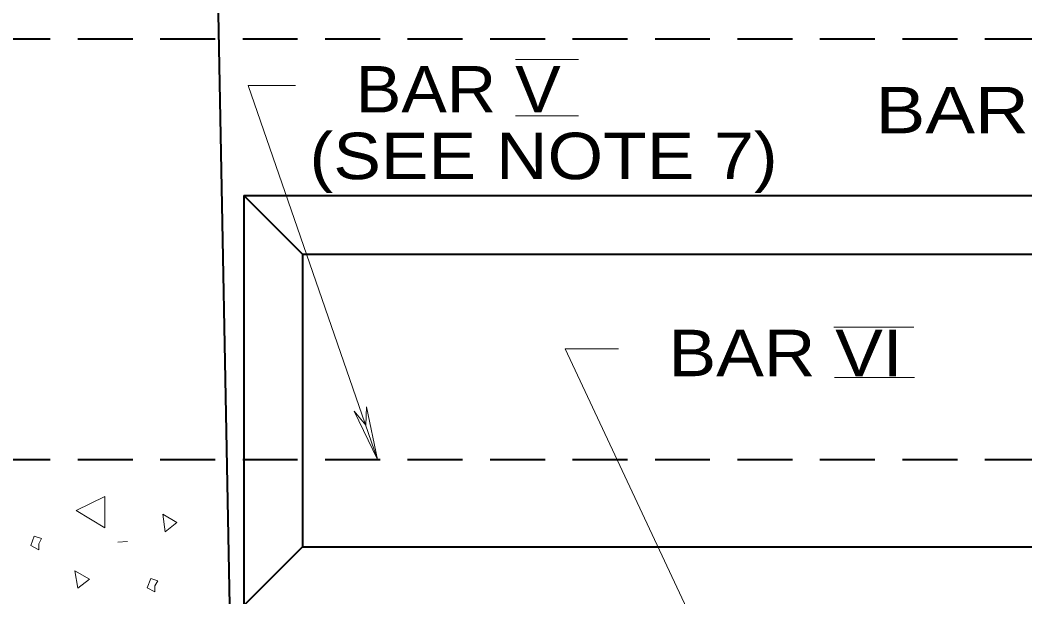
# Model space of a CAD drawing. Extents: x 312583 to 312854, y 144419 to 144597.
# Drawn here: x 312643.91 to 312660.36, y 144455.06 to 144464.5 of the extents above; entities that cross this region are included whole.
import ezdxf

# ---------------------------------------------------------------- set-up
doc = ezdxf.new("R2010")
doc.units = 0
doc.header["$LTSCALE"] = 0.3
doc.linetypes.add('MEDIUM_DASHED', pattern=[4.5, 3, -1.5])
doc.layers.add('1', color=7, linetype='Continuous', lineweight=25)
doc.layers.add('2', color=7, linetype='Continuous', lineweight=13)

msp = doc.modelspace()

# ---------------------------------------------------------------- linework, layer by layer
at = {"layer": '1', "lineweight": 40}
for p, q in [((312646.6198, 144493.0154), (312647.3405, 144454.9198)), ((312647.5781, 144461.6281), (312662.9115, 144461.6281)), ((312647.5781, 144461.6281), (312647.5781, 144454.9198)), ((312648.5365, 144460.6698), (312647.5781, 144461.6281)), ((312648.5365, 144460.6698), (312661.9531, 144460.6698)), ((312648.5365, 144460.6698), (312648.5365, 144455.8781)), ((312648.5365, 144455.8781), (312647.5781, 144454.9198)), ((312648.5365, 144455.8781), (312661.9531, 144455.8781))]:
    msp.add_line(p, q, dxfattribs=at)
at = {"layer": '1', "linetype": 'MEDIUM_DASHED', "lineweight": 40}
for p, q in [((312643.5071, 144464.1888), (312667.7031, 144464.1888)), ((312643.5071, 144457.3118), (312667.7031, 144457.3118))]:
    msp.add_line(p, q, dxfattribs=at)
at = {"layer": '1', "lineweight": 13}
msp.add_line((312645.5158, 144455.9548), (312645.6691, 144455.9701), dxfattribs=at)
for points in [[(312645.3011, 144456.1924), (312645.3011, 144456.7061), (312644.8335, 144456.4761)], [(312646.2901, 144456.1234), (312646.4818, 144456.2768), (312646.2518, 144456.4148)], [(312644.2201, 144455.9318), (312644.2661, 144456.0161), (312644.1435, 144456.0544), (312644.0898, 144455.9011), (312644.2201, 144455.8321)], [(312644.8565, 144455.2034), (312645.0481, 144455.3491), (312644.8105, 144455.4871)], [(312646.1215, 144455.2418), (312646.1675, 144455.3261), (312646.0525, 144455.3644), (312645.9911, 144455.2111), (312646.1215, 144455.1421)]]:
    msp.add_lwpolyline(points, close=True, dxfattribs=at)
at = {"layer": '2'}
for p, q in [((312652.0248, 144463.8514), (312653.0521, 144463.8514)), ((312647.6471, 144463.4298), (312649.7631, 144457.3118)), ((312648.4215, 144463.4298), (312647.6471, 144463.4298)), ((312652.0248, 144462.9314), (312653.0521, 144462.9314)), ((312657.2356, 144459.4754), (312658.5466, 144459.4754)), ((312652.8375, 144459.1211), (312655.2448, 144453.9844)), ((312653.7115, 144459.1211), (312652.8375, 144459.1211)), ((312657.2445, 144458.653), (312658.5555, 144458.653)), ((312649.3798, 144458.1014), (312649.5715, 144457.8714)), ((312649.7631, 144457.3118), (312649.3798, 144458.1014)), ((312649.5868, 144458.1704), (312649.5715, 144457.8714)), ((312649.7631, 144457.3118), (312649.5868, 144458.1704))]:
    msp.add_line(p, q, dxfattribs=at)

# ---------------------------------------------------------------- texts
for s, width, p in [('BAR V', 1.1, (312649.4086, 144462.9861)), ('BAR VII', 1.2, (312657.9188, 144462.6458)), ('(SEE NOTE 7)', 1.15, (312648.6515, 144461.8954)), ('BAR VI', 1.15, (312654.5295, 144458.6722))]:
    msp.add_text(s, height=0.76, dxfattribs=dict(at, width=width)).set_placement(p)

doc.saveas('drawing.dxf')
